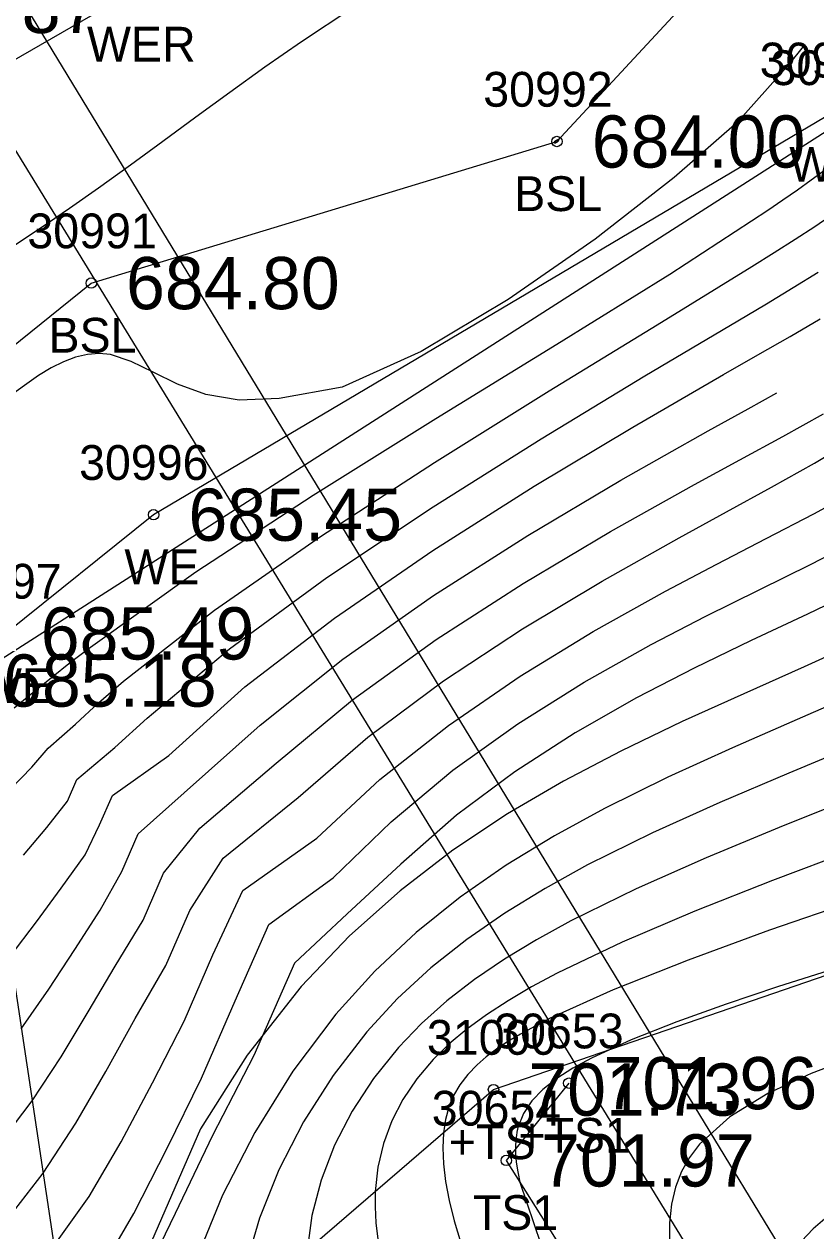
# Model space of a CAD drawing. Extents: x 1376587 to 1378239, y 1000335 to 1003031.
# Drawn here: x 1377347.4 to 1377370.14, y 1001634.22 to 1001668.9 of the extents above; entities that cross this region are included whole.
import ezdxf

# ---------------------------------------------------------------- set-up
doc = ezdxf.new("R2010")
doc.units = 0
for name, color, linetype in [('RD_DTM_BkLn2', 7, 'Continuous'), ('RD_DTM_BkLn_txCode', 7, 'Continuous'), ('RD_DTM_Major1', 7, 'Continuous'), ('RD_DTM_Minor1', 7, 'Continuous'), ('RD_EX_Bridge', 7, 'Continuous'), ('RD_EX_H2O', 7, 'Continuous'), ('RD_EX_H2O_txCode', 7, 'Continuous'), ('RD_EX_TX_H2O_ELEV', 7, 'Continuous'), ('RD_EX_TX_Misc_ELEV', 7, 'Continuous'), ('RD_SMD_Locator', 7, 'Continuous')]:
    doc.layers.add(name, color=color, linetype=linetype)

msp = doc.modelspace()

# ---------------------------------------------------------------- linework, layer by layer
at = {"layer": 'RD_DTM_BkLn2'}
for points in [[(1377322.969, 1001642.525), (1377338.521, 1001652.749), (1377349.324, 1001661.46), (1377362.701, 1001665.53), (1377372.438, 1001676.042), (1377380.468, 1001695.811), (1377383.451, 1001707.403)], [(1377349.116, 1001628.131), (1377360.879, 1001638.279), (1377377.905, 1001644.134), (1377389.827, 1001652.199), (1377380.982, 1001666.365), (1377388.117, 1001678.544), (1377396.047, 1001693.167)], [(1377363.04, 1001638.463), (1377361.246, 1001636.243), (1377387.71, 1001594.226), (1377407.172, 1001565.016), (1377420.745, 1001544.524), (1377441.371, 1001508.673), (1377461.132, 1001479.016), (1377484.313, 1001440.71), (1377503.742, 1001407.975), (1377518.283, 1001383.961), (1377528.112, 1001362.148), (1377529.648, 1001353.442)]]:
    msp.add_lwpolyline(points, dxfattribs=at)
at = {"layer": 'RD_DTM_Major1'}
for points in [[(1377347.009, 1001662.474), (1377347.858, 1001663.041), (1377348.698, 1001663.612), (1377349.534, 1001664.195), (1377350.454, 1001664.857), (1377351.383, 1001665.539), (1377352.329, 1001666.237), (1377353.301, 1001666.95), (1377354.308, 1001667.673), (1377355.359, 1001668.403), (1377356.808, 1001669.364)], [(1377369.809, 1001668.304), (1377369.307, 1001667.674), (1377367.877, 1001666.078), (1377366.067, 1001664.495), (1377363.798, 1001662.724), (1377361.3, 1001660.984), (1377358.802, 1001659.493), (1377356.533, 1001658.473), (1377354.721, 1001658.141)], [(1377354.721, 1001658.141), (1377353.574, 1001658.091), (1377352.614, 1001658.255), (1377351.802, 1001658.551), (1377351.1, 1001658.895), (1377350.471, 1001659.207), (1377349.878, 1001659.403), (1377349.547, 1001659.435), (1377349.214, 1001659.409), (1377348.876, 1001659.33), (1377348.53, 1001659.2), (1377348.175, 1001659.025), (1377347.809, 1001658.807), (1377346.832, 1001658.1)], [(1377347.311, 1001640.027), (1377348.11, 1001641.167), (1377348.853, 1001642.303), (1377349.585, 1001643.435), (1377350.199, 1001644.545), (1377350.674, 1001645.631), (1377351.997, 1001646.804), (1377354.174, 1001648.753), (1377356.551, 1001650.651), (1377359.158, 1001652.48), (1377361.865, 1001654.206), (1377364.539, 1001655.795), (1377367.049, 1001657.214), (1377368.195, 1001657.846), (1377369.019, 1001658.301)], [(1377371.452, 1001652.691), (1377369.894, 1001651.945), (1377368.284, 1001651.185), (1377366.641, 1001650.391), (1377364.985, 1001649.537), (1377363.223, 1001648.534), (1377361.491, 1001647.416), (1377359.814, 1001646.165), (1377358.214, 1001644.759), (1377356.675, 1001643.331), (1377355.158, 1001641.915), (1377353.998, 1001639.26), (1377352.807, 1001636.962), (1377351.73, 1001634.719), (1377350.738, 1001632.655)], [(1377375.721, 1001646.826), (1377375.607, 1001646.783), (1377373.446, 1001645.986), (1377371.182, 1001645.153), (1377368.894, 1001644.292), (1377366.665, 1001643.411), (1377364.575, 1001642.519), (1377362.707, 1001641.624), (1377361.973, 1001641.229), (1377361.296, 1001640.832), (1377360.677, 1001640.429), (1377360.113, 1001640.016), (1377359.605, 1001639.59), (1377359.15, 1001639.146), (1377358.674, 1001638.586), (1377358.276, 1001637.996), (1377357.957, 1001637.378), (1377357.717, 1001636.73), (1377357.558, 1001636.053), (1377357.482, 1001635.348), (1377357.476, 1001634.907), (1377357.5, 1001634.452), (1377357.556, 1001633.98)]]:
    msp.add_lwpolyline(points, dxfattribs=at)
at = {"layer": 'RD_DTM_Minor1'}
for points in [[(1377347.112, 1001649.248), (1377347.643, 1001649.691), (1377348.181, 1001650.128), (1377348.732, 1001650.563), (1377349.301, 1001651), (1377352.329, 1001653.157), (1377355.698, 1001655.364), (1377359.218, 1001657.564), (1377362.697, 1001659.7), (1377365.942, 1001661.715), (1377368.763, 1001663.553), (1377369.194, 1001663.849), (1377369.607, 1001664.139), (1377370.006, 1001664.425), (1377370.39, 1001664.709), (1377370.762, 1001664.993), (1377371.123, 1001665.277), (1377371.573, 1001665.645), (1377372.011, 1001666.02), (1377372.441, 1001666.405), (1377372.866, 1001666.803), (1377373.291, 1001667.216), (1377373.718, 1001667.647), (1377375.301, 1001669.365)], [(1377362.763, 1001665.597), (1377362.759, 1001665.6), (1377362.753, 1001665.599), (1377362.734, 1001665.59), (1377362.698, 1001665.568), (1377362.687, 1001665.56), (1377362.675, 1001665.554), (1377362.664, 1001665.547), (1377362.654, 1001665.541), (1377362.645, 1001665.535), (1377362.637, 1001665.529), (1377362.63, 1001665.524), (1377362.624, 1001665.519), (1377362.62, 1001665.514), (1377362.618, 1001665.509), (1377362.618, 1001665.505), (1377362.619, 1001665.501), (1377362.622, 1001665.498), (1377362.626, 1001665.495), (1377362.632, 1001665.493), (1377362.638, 1001665.491), (1377362.646, 1001665.491), (1377362.657, 1001665.492), (1377362.67, 1001665.495), (1377362.683, 1001665.5), (1377362.697, 1001665.508), (1377362.712, 1001665.519), (1377362.737, 1001665.544), (1377362.746, 1001665.557), (1377362.755, 1001665.57), (1377362.76, 1001665.582), (1377362.763, 1001665.592), (1377362.763, 1001665.597)], [(1377347.002, 1001646.914), (1377347.621, 1001647.549), (1377348.083, 1001648.09), (1377348.872, 1001648.781), (1377349.537, 1001649.394), (1377350.251, 1001650.016), (1377352.864, 1001652.054), (1377355.91, 1001654.176), (1377359.182, 1001656.304), (1377362.474, 1001658.359), (1377365.582, 1001660.261), (1377368.298, 1001661.933), (1377368.938, 1001662.336), (1377369.539, 1001662.72), (1377370.104, 1001663.091), (1377370.638, 1001663.453)], [(1377347.383, 1001645.012), (1377348.051, 1001645.816), (1377348.642, 1001646.573), (1377348.909, 1001647.187), (1377349.998, 1001648.111), (1377350.935, 1001648.95), (1377353.298, 1001650.944), (1377356.096, 1001652.994), (1377359.142, 1001655.031), (1377362.248, 1001656.986), (1377365.228, 1001658.791), (1377367.893, 1001660.376), (1377368.718, 1001660.867), (1377369.487, 1001661.331), (1377370.205, 1001661.775)], [(1377346.996, 1001642.103), (1377347.751, 1001643.096), (1377348.457, 1001644.068), (1377349.153, 1001645.024), (1377349.563, 1001645.884), (1377349.932, 1001646.73), (1377351.556, 1001647.885), (1377353.732, 1001649.852), (1377356.313, 1001651.833), (1377359.14, 1001653.773), (1377362.051, 1001655.621), (1377364.885, 1001657.323), (1377367.482, 1001658.828), (1377368.473, 1001659.394), (1377369.399, 1001659.926), (1377370.265, 1001660.434)], [(1377346.577, 1001636.572), (1377347.626, 1001637.951), (1377348.459, 1001639.217), (1377349.237, 1001640.513), (1377350.009, 1001641.828), (1377350.812, 1001643.15), (1377351.399, 1001644.496), (1377352.439, 1001645.793), (1377354.64, 1001647.664), (1377356.828, 1001649.484), (1377359.227, 1001651.212), (1377361.733, 1001652.83), (1377364.243, 1001654.324), (1377366.656, 1001655.675), (1377367.951, 1001656.379), (1377369.185, 1001657.05), (1377370.36, 1001657.706)], [(1377346.965, 1001634.613), (1377347.941, 1001635.875), (1377348.881, 1001637.31), (1377349.745, 1001638.799), (1377350.587, 1001640.319), (1377351.463, 1001641.847), (1377352.155, 1001643.427), (1377353.112, 1001644.93), (1377355.271, 1001646.675), (1377357.269, 1001648.408), (1377359.445, 1001650.025), (1377361.716, 1001651.522), (1377363.999, 1001652.895), (1377366.212, 1001654.142), (1377367.572, 1001654.884), (1377368.868, 1001655.59), (1377370.099, 1001656.283), (1377371.264, 1001656.98)], [(1377348.256, 1001633.799), (1377349.263, 1001635.202), (1377350.187, 1001636.777), (1377351.087, 1001638.468), (1377351.989, 1001640.249), (1377352.817, 1001642.15), (1377353.678, 1001643.998), (1377355.804, 1001645.501), (1377357.615, 1001647.194), (1377359.582, 1001648.746), (1377361.645, 1001650.161), (1377363.743, 1001651.445), (1377365.818, 1001652.605), (1377367.292, 1001653.381), (1377368.715, 1001654.115), (1377370.081, 1001654.828), (1377371.386, 1001655.54)], [(1377349.591, 1001633.065), (1377350.551, 1001634.721), (1377351.504, 1001636.592), (1377352.492, 1001638.603), (1377353.461, 1001640.828), (1377354.422, 1001643.027), (1377356.274, 1001644.369), (1377357.941, 1001645.975), (1377359.712, 1001647.456), (1377361.573, 1001648.79), (1377363.483, 1001649.989), (1377365.404, 1001651.068), (1377366.973, 1001651.883), (1377368.508, 1001652.647), (1377369.999, 1001653.384), (1377371.431, 1001654.115)], [(1377371.492, 1001651.193), (1377369.805, 1001650.43), (1377368.067, 1001649.657), (1377366.302, 1001648.856), (1377364.535, 1001648.004), (1377362.894, 1001647.142), (1377361.283, 1001646.2), (1377359.713, 1001645.157), (1377358.194, 1001643.996), (1377356.738, 1001642.697), (1377355.354, 1001641.239), (1377353.806, 1001639.269), (1377352.467, 1001637.149), (1377351.534, 1001635.012), (1377350.543, 1001632.742)], [(1377371.422, 1001649.71), (1377369.598, 1001648.916), (1377367.74, 1001648.105), (1377365.883, 1001647.26), (1377364.063, 1001646.361), (1377362.627, 1001645.575), (1377361.244, 1001644.728), (1377359.919, 1001643.805), (1377358.658, 1001642.794), (1377357.466, 1001641.679), (1377356.348, 1001640.448), (1377355.112, 1001638.806), (1377354.019, 1001637.048), (1377353.094, 1001635.243), (1377352.366, 1001633.465)], [(1377371.331, 1001648.195), (1377369.362, 1001647.371), (1377367.384, 1001646.529), (1377365.442, 1001645.655), (1377363.583, 1001644.735), (1377362.361, 1001644.061), (1377361.202, 1001643.35), (1377360.109, 1001642.591), (1377359.083, 1001641.776), (1377358.125, 1001640.895), (1377357.239, 1001639.939), (1377356.27, 1001638.685), (1377355.422, 1001637.348), (1377354.711, 1001635.968), (1377354.153, 1001634.585), (1377353.765, 1001633.238)], [(1377371.205, 1001646.662), (1377369.084, 1001645.809), (1377366.987, 1001644.939), (1377364.974, 1001644.049), (1377363.104, 1001643.13), (1377362.115, 1001642.587), (1377361.193, 1001642.027), (1377360.335, 1001641.444), (1377359.542, 1001640.831), (1377358.813, 1001640.182), (1377358.149, 1001639.492), (1377357.435, 1001638.602), (1377356.821, 1001637.659), (1377356.315, 1001636.678), (1377355.925, 1001635.674), (1377355.658, 1001634.662), (1377355.523, 1001633.658)], [(1377386.695, 1001644.152), (1377385.651, 1001643.576), (1377384.524, 1001642.912), (1377383.331, 1001642.183), (1377380.813, 1001640.615), (1377379.521, 1001639.82), (1377378.312, 1001639.094), (1377377.117, 1001638.394), (1377375.949, 1001637.724), (1377374.823, 1001637.091), (1377373.752, 1001636.501), (1377372.751, 1001635.959), (1377372.098, 1001635.608), (1377371.493, 1001635.274), (1377370.946, 1001634.948), (1377370.465, 1001634.62), (1377370.056, 1001634.28), (1377369.73, 1001633.919)], [(1377371.211, 1001643.685), (1377368.81, 1001642.857), (1377366.466, 1001642.001), (1377364.313, 1001641.146), (1377362.485, 1001640.318), (1377362.053, 1001640.096), (1377361.656, 1001639.876), (1377361.293, 1001639.657), (1377360.965, 1001639.438), (1377360.671, 1001639.216), (1377360.409, 1001638.989), (1377360.139, 1001638.708), (1377359.914, 1001638.415), (1377359.733, 1001638.105), (1377359.595, 1001637.775), (1377359.499, 1001637.421), (1377359.441, 1001637.038), (1377359.421, 1001636.609), (1377359.442, 1001636.144), (1377359.504, 1001635.64), (1377359.607, 1001635.095), (1377359.752, 1001634.507), (1377359.939, 1001633.875)], [(1377370.518, 1001641.704), (1377369.038, 1001641.229), (1377367.563, 1001640.737), (1377366.145, 1001640.229), (1377364.837, 1001639.71), (1377363.693, 1001639.183), (1377363.16, 1001638.894), (1377362.694, 1001638.597), (1377362.299, 1001638.285), (1377361.98, 1001637.951), (1377361.739, 1001637.589), (1377361.582, 1001637.193), (1377361.578, 1001637.179), (1377361.575, 1001637.166), (1377361.572, 1001637.153), (1377361.568, 1001637.14), (1377361.565, 1001637.126), (1377361.562, 1001637.113), (1377361.525, 1001636.904), (1377361.508, 1001636.683), (1377361.511, 1001636.447), (1377361.533, 1001636.192), (1377361.576, 1001635.917), (1377361.639, 1001635.62), (1377362.444, 1001633.243)], [(1377371.361, 1001639.256), (1377370.008, 1001638.745), (1377368.755, 1001638.169), (1377367.663, 1001637.5), (1377366.795, 1001636.708), (1377366.511, 1001636.33), (1377366.28, 1001635.92), (1377366.105, 1001635.474), (1377365.987, 1001634.985), (1377365.93, 1001634.449), (1377365.935, 1001633.86)]]:
    msp.add_lwpolyline(points, dxfattribs=at)
at = {"layer": 'RD_EX_Bridge'}
for points in [[(1377391.499, 1001645.129), (1377368.188, 1001630.936), (1377328.998, 1001694.929), (1377352.485, 1001709.161), (1377391.541, 1001645.169)], [(1377331.327, 1001695.905), (1377370.084, 1001632.15)]]:
    msp.add_lwpolyline(points, dxfattribs=at)
at = {"layer": 'RD_EX_H2O'}
for points in [[(1377375.48, 1001712.375), (1377377.18, 1001695.925), (1377371.091, 1001691.175), (1377365.495, 1001678.948), (1377350.495, 1001669.827), (1377334.456, 1001660.576)], [(1377385.629, 1001693.938), (1377384.621, 1001693.635), (1377383.547, 1001681.612), (1377370.643, 1001666.371), (1377351.116, 1001654.803), (1377346.874, 1001651.39)], [(1377396.047, 1001693.167), (1377388.971, 1001691.891), (1377383.547, 1001681.612), (1377370.954, 1001666.151), (1377345.792, 1001650.036), (1377349.116, 1001628.131), (1377334.126, 1001625.317), (1377311.323, 1001589.505), (1377259.373, 1001541.156), (1377186.141, 1001542.199), (1377119.382, 1001530.527), (1377065.136, 1001518.284), (1377035.175, 1001514.747), (1376967.402, 1001521.021), (1376926.832, 1001536.774)]]:
    msp.add_lwpolyline(points, dxfattribs=at)
at = {"layer": 'RD_SMD_Locator'}
for centre in [(1377362.701, 1001665.53), (1377349.324, 1001661.46), (1377351.116, 1001654.803), (1377363.04, 1001638.463), (1377360.879, 1001638.279), (1377361.246, 1001636.243)]:
    msp.add_circle(centre, 0.15, dxfattribs=at)

# ---------------------------------------------------------------- texts
at = {"layer": 'RD_DTM_BkLn_txCode'}
for s, p in [('30998', (1377368.835, 1001667.151)), ('30992', (1377360.583, 1001666.53)), ('BSL', (1377361.473, 1001663.53)), ('30991', (1377347.489, 1001662.46)), ('BSL', (1377348.096, 1001659.46)), ('31000', (1377358.966, 1001639.279)), ('30653', (1377360.898, 1001639.463)), ('30654', (1377359.104, 1001637.243)), ('+TS1', (1377361.591, 1001636.463)), ('+TS', (1377359.596, 1001636.279)), ('TS1', (1377360.285, 1001634.243))]:
    msp.add_text(s, height=1, dxfattribs=at).set_placement(p)
at = {"layer": 'RD_EX_H2O_txCode'}
for s, p in [('WER', (1377349.204, 1001667.827)), ('30995', (1377368.525, 1001667.371)), ('WEL', (1377369.375, 1001664.371)), ('30996', (1377348.974, 1001655.803)), ('WE', (1377350.277, 1001652.803)), ('30997', (1377344.756, 1001652.39)), ('-WE', (1377345.626, 1001649.39))]:
    msp.add_text(s, height=1, dxfattribs=at).set_placement(p)
at = {"layer": 'RD_EX_TX_H2O_ELEV'}
for s, p in [('685.45', (1377352.116, 1001654.053)), ('685.49', (1377347.874, 1001650.64))]:
    msp.add_text(s, height=1.5, dxfattribs=at).set_placement(p)
at = {"layer": 'RD_EX_TX_Misc_ELEV'}
for s, p in [('687.87', (1377343.423, 1001668.648)), ('684.00', (1377363.701, 1001664.78)), ('684.80', (1377350.324, 1001660.71)), ('685.18', (1377346.792, 1001649.286)), ('701.96', (1377364.04, 1001637.713)), ('701.73', (1377361.879, 1001637.529)), ('701.97', (1377362.246, 1001635.493))]:
    msp.add_text(s, height=1.5, dxfattribs=at).set_placement(p)

doc.saveas('drawing.dxf')
